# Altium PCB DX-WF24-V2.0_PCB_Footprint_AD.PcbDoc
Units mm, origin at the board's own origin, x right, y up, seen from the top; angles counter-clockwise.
Board outline 152.4 x 101.6 mm, 2 copper layers (Top, Bottom), stack 0.323 mm thick; 1 components, 0 nets, 29 pads, 0 vias.
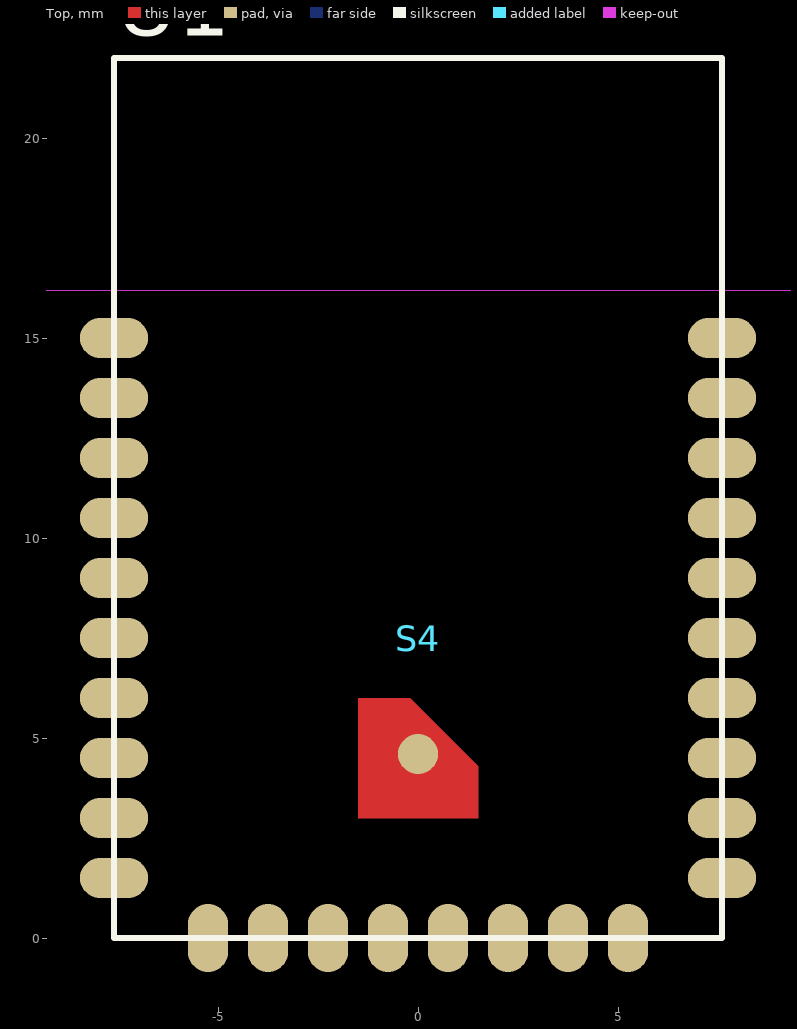
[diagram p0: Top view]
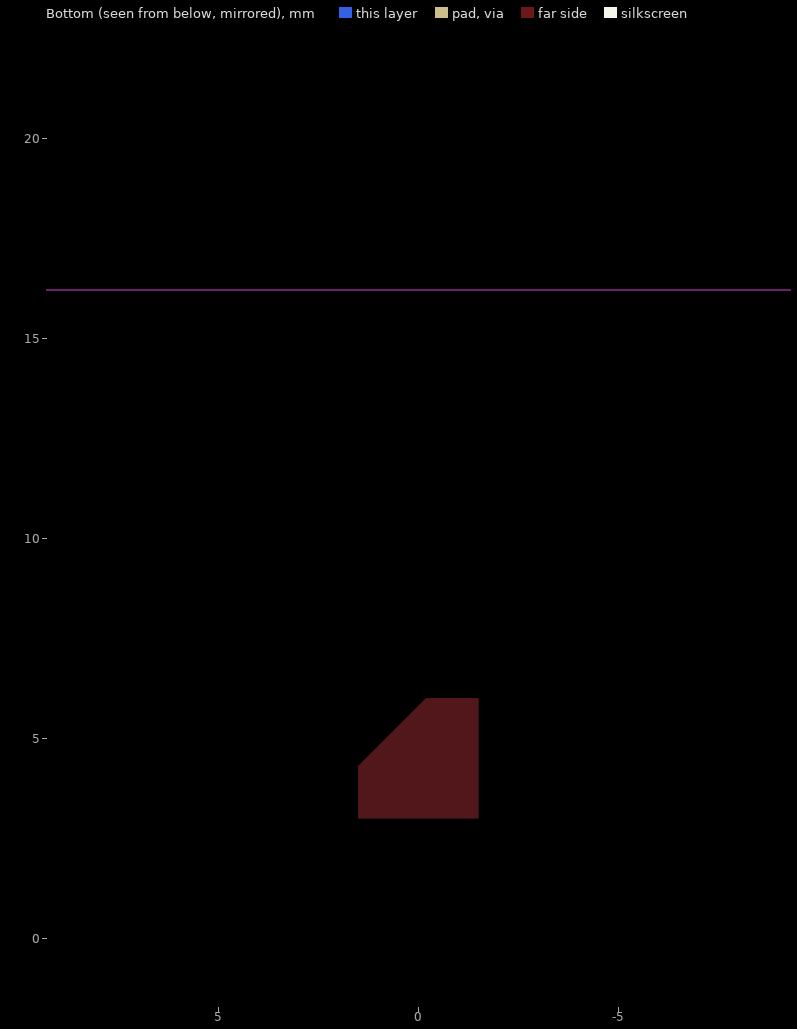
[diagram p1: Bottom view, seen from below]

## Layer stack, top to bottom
Solder Mask Top: solder mask 0.0102, Solder Resist, Dk 3.5
Top: signal copper 0.0343
Dielectric 1: dielectric 0.254, FR-4, Dk 4.3
Bottom: signal copper 0.0343
Solder Mask Bottom: solder mask 0.0102, Solder Resist, Dk 3.5

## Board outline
-694.363,-676.631 -541.963,-676.631 -541.963,-575.031 -694.363,-575.031

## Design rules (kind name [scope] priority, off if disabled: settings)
Clearance "'Default' PADS rule_17" [All] p1: gap=0.152 ignorepadtopadclearanceinfootprint=FALSE except(0: Arc-Hole Track-Hole SMDPad-Hole THPad-Hole Via-Hole Fill-Hole Poly-Hole Region-Hole Text-Hole)
Clearance "'Default' PADS rule_16" [InPolygon vs InPolygon] p2: gap=0.2 ignorepadtopadclearanceinfootprint=FALSE except(0: Arc-Hole Track-Hole SMDPad-Hole THPad-Hole Via-Hole Fill-Hole Poly-Hole Region-Hole Text-Hole)
Clearance "'Default' PADS rule_15" [All] p3: gap=0.152 ignorepadtopadclearanceinfootprint=FALSE except(0: Arc-Hole Track-Hole SMDPad-Hole THPad-Hole Via-Hole Fill-Hole Poly-Hole Region-Hole Text-Hole)
ComponentClearance "'Default' PADS rule_12" [All] p1: gap=0 collisioncheckmode=3 verticalgap=0.254 showdistances=FALSE
FlightTimeFalling "'Default' PADS rule_10" [All] p1: maximum=10.00
FlightTimeRising "'Default' PADS rule_9" [All] p1: maximum=10.00
Length "'Default' PADS rule_5" [All] p1: maxlimit=1270 minlimit=0
MatchedLengths "'Default' PADS rule_11" [InNetClass('All Nets')] p1: tolerance=5.08 checknetsindiffpair=TRUE checkdiffpairvsdiffpair=FALSE checkxsignals=FALSE checkothers=FALSE
MaxMinImpedance "'Default' PADS rule_8" [All] p1: minimum=50.00 maximum=150.0
ParallelSegment "'Default' PADS rule_7" [All] p1: limit=25.4 gap=5.08
ParallelSegment "'Default' PADS rule_6" [All] p2: limit=25.4 gap=5.08
PlaneClearance "'Default' PADS rule_14" [All] p1: clearance=0.2
PlaneConnect "Power Plane Connect Style - Via from round thru-hole global defaults" [IsVia] p1: planeconnectstyle=Direct reliefexpansion=0.508 reliefentries=4 reliefconductorwidth=0.381 reliefairgap=0.254
PlaneConnect "Power Plane Connect Style - Round thru-hole pad from global defaults" [IsPad And OnMultiLayer And (PadShape_MidLayer1 = 'Round') And (PadXSize_MidLayer1 = PadYSize_MidLayer1)] p2: planeconnectstyle=Direct reliefexpansion=0.508 reliefentries=4 reliefconductorwidth=0.381 reliefairgap=0.254
PlaneConnect "Power Plane Connect Style - Square thru-hole pad from global defaults" [IsPad And OnMultiLayer And ((PadShape_MidLayer1 = 'Rectangular') Or (PadShape_MidLayer1 = 'Octagonal') Or (PadShape_MidLayer1 = 'Rounded Rectangle')) And (PadXSize_MidLayer1 = PadYSize_MidLayer1)] p3: planeconnectstyle=Direct reliefexpansion=0.508 reliefentries=4 reliefconductorwidth=0.381 reliefairgap=0.254
PlaneConnect "Power Plane Connect Style - Rect thru-hole pad from global defaults" [IsPad And OnMultiLayer And ((PadShape_MidLayer1 = 'Rectangular') Or (PadShape_MidLayer1 = 'Octagonal') Or (PadShape_MidLayer1 = 'Rounded Rectangle')) And (PadXSize_MidLayer1 <> PadYSize_MidLayer1)] p4: planeconnectstyle=Direct reliefexpansion=0.508 reliefentries=4 reliefconductorwidth=0.381 reliefairgap=0.254
PlaneConnect "Power Plane Connect Style - Square-rect thru-hole pad from global defaults" [IsPad And OnMultiLayer And (PadShape_MidLayer1 = 'Rounded Rectangle') And (PadXSize_MidLayer1 = PadYSize_MidLayer1) And (Pad_CornerRadius_MidLayer1 = '0%')] p5: planeconnectstyle=Direct reliefexpansion=0.508 reliefentries=4 reliefconductorwidth=0.381 reliefairgap=0.254
PlaneConnect "Power Plane Connect Style - Oval thru-hole pad from global defaults" [IsPad And OnMultiLayer And (PadShape_MidLayer1 = 'Round') And (PadXSize_MidLayer1 <> PadYSize_MidLayer1)] p6: planeconnectstyle=Direct reliefexpansion=0.508 reliefentries=4 reliefconductorwidth=0.381 reliefairgap=0.254
PlaneConnect "Power Plane Connect Style - Round-oval thru-hole pad from global defaults" [IsPad And OnMultiLayer And (PadShape_MidLayer1 = 'Rounded Rectangle') And (PadXSize_MidLayer1 = PadYSize_MidLayer1) And (Pad_CornerRadius_MidLayer1 = '100%')] p7: planeconnectstyle=Direct reliefexpansion=0.508 reliefentries=4 reliefconductorwidth=0.381 reliefairgap=0.254
PolygonConnect "Polygon Connect Style - Bottom Round SMD from global defaults" [IsSMTPin And (PadShape_BottomLayer = 'Round') And (PadXSize_BottomLayer = PADYSize_BottomLayer) vs Layer = 'Bottom'] p1: connectstyle=Direct reliefconductorwidth=0.254 reliefentries=4 polygonreliefangle="45 Angle" airgapwidth=0.254
PolygonConnect "Polygon Connect Style - Top Round SMD from global defaults" [IsSMTPin And (PadShape_TopLayer = 'Round') And (PadXSize_TopLayer = PADYSize_TopLayer) vs Layer = 'Top'] p2: connectstyle=Direct reliefconductorwidth=0.254 reliefentries=4 polygonreliefangle="45 Angle" airgapwidth=0.254
PolygonConnect "Polygon Connect Style - Bottom Square SMD from global defaults 1" [IsSMTPin And (PadShape_BottomLayer = 'Rectangular') And (PadXSize_BottomLayer = PADYSize_BottomLayer) vs Layer = 'Bottom'] p3: connectstyle=Direct reliefconductorwidth=0.254 reliefentries=4 polygonreliefangle="45 Angle" airgapwidth=0.254
PolygonConnect "Polygon Connect Style - Bottom Square SMD from global defaults 2" [IsSMTPin And (PadShape_BottomLayer = 'Octagonal') And (PadXSize_BottomLayer = PADYSize_BottomLayer) vs Layer = 'Bottom'] p4: connectstyle=Direct reliefconductorwidth=0.254 reliefentries=4 polygonreliefangle="45 Angle" airgapwidth=0.254
PolygonConnect "Polygon Connect Style - Bottom Square SMD from global defaults 3" [IsSMTPin And (PadShape_BottomLayer = 'Rounded Rectangle') And (PadXSize_BottomLayer = PADYSize_BottomLayer) vs Layer = 'Bottom'] p5: connectstyle=Direct reliefconductorwidth=0.254 reliefentries=4 polygonreliefangle="45 Angle" airgapwidth=0.254
PolygonConnect "Polygon Connect Style - Top Square SMD from global defaults 1" [IsSMTPin And (PadShape_TopLayer = 'Rectangular') And (PadXSize_TopLayer = PADYSize_TopLayer) vs Layer = 'Top'] p6: connectstyle=Direct reliefconductorwidth=0.254 reliefentries=4 polygonreliefangle="45 Angle" airgapwidth=0.254
PolygonConnect "Polygon Connect Style - Top Square SMD from global defaults 2" [IsSMTPin And (PadShape_TopLayer = 'Octagonal') And (PadXSize_TopLayer = PADYSize_TopLayer) vs Layer = 'Top'] p7: connectstyle=Direct reliefconductorwidth=0.254 reliefentries=4 polygonreliefangle="45 Angle" airgapwidth=0.254
PolygonConnect "Polygon Connect Style - Top Square SMD from global defaults 3" [IsSMTPin And (PadShape_TopLayer = 'Rounded Rectangle') And (PadXSize_TopLayer = PADYSize_TopLayer) vs Layer = 'Top'] p8: connectstyle=Direct reliefconductorwidth=0.254 reliefentries=4 polygonreliefangle="45 Angle" airgapwidth=0.254
PolygonConnect "Polygon Connect Style - Bottom Rect SMD from global defaults 1" [IsSMTPin And (PadShape_BottomLayer = 'Rectangular') And (PadXSize_BottomLayer <> PADYSize_BottomLayer) vs Layer = 'Bottom'] p9: connectstyle=Direct reliefconductorwidth=0.254 reliefentries=4 polygonreliefangle="45 Angle" airgapwidth=0.254
PolygonConnect "Polygon Connect Style - Bottom Rect SMD from global defaults 2" [IsSMTPin And (PadShape_BottomLayer = 'Octagonal') And (PadXSize_BottomLayer <> PADYSize_BottomLayer) vs Layer = 'Bottom'] p10: connectstyle=Direct reliefconductorwidth=0.254 reliefentries=4 polygonreliefangle="45 Angle" airgapwidth=0.254
PolygonConnect "Polygon Connect Style - Bottom Rect SMD from global defaults 3" [IsSMTPin And (PadShape_BottomLayer = 'Rounded Rectangle') And (PadXSize_BottomLayer <> PADYSize_BottomLayer) vs Layer = 'Bottom'] p11: connectstyle=Direct reliefconductorwidth=0.254 reliefentries=4 polygonreliefangle="45 Angle" airgapwidth=0.254
PolygonConnect "Polygon Connect Style - Bottom Square-rect SMD pad from global defaults" [IsSMTPin And (PadShape_BottomLayer = 'Rounded Rectangle') And (PadXSize_BottomLayer = PADYSize_BottomLayer) And (Pad_CornerRadius_BottomLayer = '0%') vs Layer = 'Bottom'] p12: connectstyle=Direct reliefconductorwidth=0.254 reliefentries=4 polygonreliefangle="45 Angle" airgapwidth=0.254
PolygonConnect "Polygon Connect Style - Top Rect SMD from global defaults 1" [IsSMTPin And (PadShape_TopLayer = 'Rectangular') And (PadXSize_TopLayer <> PADYSize_TopLayer) vs Layer = 'Top'] p13: connectstyle=Direct reliefconductorwidth=0.254 reliefentries=4 polygonreliefangle="45 Angle" airgapwidth=0.254
PolygonConnect "Polygon Connect Style - Top Rect SMD from global defaults 2" [IsSMTPin And (PadShape_TopLayer = 'Octagonal') And (PadXSize_TopLayer <> PADYSize_TopLayer) vs Layer = 'Top'] p14: connectstyle=Direct reliefconductorwidth=0.254 reliefentries=4 polygonreliefangle="45 Angle" airgapwidth=0.254
PolygonConnect "Polygon Connect Style - Top Rect SMD from global defaults 3" [IsSMTPin And (PadShape_TopLayer = 'Rounded Rectangle') And (PadXSize_TopLayer <> PADYSize_TopLayer) vs Layer = 'Top'] p15: connectstyle=Direct reliefconductorwidth=0.254 reliefentries=4 polygonreliefangle="45 Angle" airgapwidth=0.254
PolygonConnect "Polygon Connect Style - Top Square-rect SMD pad from global defaults" [IsSMTPin And (PadShape_TopLayer = 'Rounded Rectangle') And (PadXSize_TopLayer = PADYSize_TopLayer) And (Pad_CornerRadius_TopLayer = '0%') vs Layer = 'Top'] p16: connectstyle=Direct reliefconductorwidth=0.254 reliefentries=4 polygonreliefangle="45 Angle" airgapwidth=0.254
PolygonConnect "Polygon Connect Style - Bottom Oval SMD from global defaults" [IsSMTPin And (PadShape_BottomLayer = 'Round') And (PadXSize_BottomLayer <> PADYSize_BottomLayer) vs Layer = 'Bottom'] p17: connectstyle=Direct reliefconductorwidth=0.254 reliefentries=4 polygonreliefangle="45 Angle" airgapwidth=0.254
PolygonConnect "Polygon Connect Style - Bottom Round-oval SMD pad from global defaults" [IsSMTPin And (PadShape_BottomLayer = 'Rounded Rectangle') And (PadXSize_BottomLayer = PADYSize_BottomLayer) And (Pad_CornerRadius_BottomLayer = '100%') vs Layer = 'Bottom'] p18: connectstyle=Direct reliefconductorwidth=0.254 reliefentries=4 polygonreliefangle="45 Angle" airgapwidth=0.254
PolygonConnect "Polygon Connect Style - Top Oval SMD from global defaults" [IsSMTPin And (PadShape_TopLayer = 'Round') And (PadXSize_TopLayer <> PADYSize_TopLayer) vs Layer = 'Top'] p19: connectstyle=Direct reliefconductorwidth=0.254 reliefentries=4 polygonreliefangle="45 Angle" airgapwidth=0.254
PolygonConnect "Polygon Connect Style - Top Round-oval SMD pad from global defaults" [IsSMTPin And (PadShape_TopLayer = 'Rounded Rectangle') And (PadXSize_TopLayer = PADYSize_TopLayer) And (Pad_CornerRadius_TopLayer = '100%') vs Layer = 'Top'] p20: connectstyle=Direct reliefconductorwidth=0.254 reliefentries=4 polygonreliefangle="45 Angle" airgapwidth=0.254
PolygonConnect "Polygon Connect Style - Via from round thru-hole global defaults_18" [IsVia] p21: connectstyle=Direct reliefconductorwidth=0.381 reliefentries=4 polygonreliefangle="45 Angle" airgapwidth=0.254
PolygonConnect "Polygon Connect Style - Bottom Round thru-hole pad from global defaults" [IsPad And OnMultiLayer And (PadShape_BottomLayer = 'Round') And (PadXSize_BottomLayer = PADYSize_BottomLayer) vs Layer = 'Bottom'] p22: connectstyle=Direct reliefconductorwidth=0.381 reliefentries=4 polygonreliefangle="45 Angle" airgapwidth=0.254
PolygonConnect "Polygon Connect Style - Via from round thru-hole global defaults" [IsVia] p23: connectstyle=Direct reliefconductorwidth=0.381 reliefentries=4 polygonreliefangle="45 Angle" airgapwidth=0.254
PolygonConnect "Polygon Connect Style - Top Round thru-hole pad from global defaults" [IsPad And OnMultiLayer And (PadShape_TopLayer = 'Round') And (PadXSize_TopLayer = PADYSize_TopLayer) vs Layer = 'Top'] p24: connectstyle=Direct reliefconductorwidth=0.381 reliefentries=4 polygonreliefangle="45 Angle" airgapwidth=0.254
PolygonConnect "Polygon Connect Style - Bottom Square thru-hole pad from global defaults" [IsPad And OnMultiLayer And ((PadShape_BottomLayer = 'Rectangular') Or (PadShape_BottomLayer = 'Octagonal') Or (PadShape_BottomLayer = 'Rounded Rectangle')) And (PadXSize_BottomLayer = PADYSize_BottomLayer) vs Layer = 'Bottom'] p25: connectstyle=Direct reliefconductorwidth=0.381 reliefentries=4 polygonreliefangle="45 Angle" airgapwidth=0.254
PolygonConnect "Polygon Connect Style - Top Square thru-hole pad from global defaults" [IsPad And OnMultiLayer And ((PadShape_TopLayer = 'Rectangular') Or (PadShape_TopLayer = 'Octagonal') Or (PadShape_TopLayer = 'Rounded Rectangle')) And (PadXSize_TopLayer = PADYSize_TopLayer) vs Layer = 'Top'] p26: connectstyle=Direct reliefconductorwidth=0.381 reliefentries=4 polygonreliefangle="45 Angle" airgapwidth=0.254
PolygonConnect "Polygon Connect Style - Bottom Rect thru-hole pad from global defaults" [IsPad And OnMultiLayer And ((PadShape_BottomLayer = 'Rectangular') Or (PadShape_BottomLayer = 'Octagonal') Or (PadShape_BottomLayer = 'Rounded Rectangle')) And (PadXSize_BottomLayer <> PADYSize_BottomLayer) vs Layer = 'Bottom'] p27: connectstyle=Direct reliefconductorwidth=0.381 reliefentries=4 polygonreliefangle="45 Angle" airgapwidth=0.254
PolygonConnect "Polygon Connect Style - Bottom Square-rect thru-hole pad from global defaults" [IsPad And OnMultiLayer And (PadShape_BottomLayer = 'Rounded Rectangle') And (PadXSize_BottomLayer = PADYSize_BottomLayer) And (Pad_CornerRadius_BottomLayer = '0%') vs Layer = 'Bottom'] p28: connectstyle=Direct reliefconductorwidth=0.381 reliefentries=4 polygonreliefangle="45 Angle" airgapwidth=0.254
PolygonConnect "Polygon Connect Style - Top Rect thru-hole pad from global defaults" [IsPad And OnMultiLayer And ((PadShape_TopLayer = 'Rectangular') Or (PadShape_TopLayer = 'Octagonal') Or (PadShape_TopLayer = 'Rounded Rectangle')) And (PadXSize_TopLayer <> PADYSize_TopLayer) vs Layer = 'Top'] p29: connectstyle=Direct reliefconductorwidth=0.381 reliefentries=4 polygonreliefangle="45 Angle" airgapwidth=0.254
PolygonConnect "Polygon Connect Style - Top Square-rect thru-hole pad from global defaults" [IsPad And OnMultiLayer And (PadShape_TopLayer = 'Rounded Rectangle') And (PadXSize_TopLayer = PADYSize_TopLayer) And (Pad_CornerRadius_TopLayer = '0%') vs Layer = 'Top'] p30: connectstyle=Direct reliefconductorwidth=0.381 reliefentries=4 polygonreliefangle="45 Angle" airgapwidth=0.254
PolygonConnect "Polygon Connect Style - Bottom Oval thru-hole pad from global defaults" [IsPad And OnMultiLayer And (PadShape_BottomLayer = 'Round') And (PadXSize_BottomLayer <> PADYSize_BottomLayer) vs Layer = 'Bottom'] p31: connectstyle=Direct reliefconductorwidth=0.381 reliefentries=4 polygonreliefangle="45 Angle" airgapwidth=0.254
PolygonConnect "Polygon Connect Style - Bottom Round-oval thru-hole pad from global defaults" [IsPad And OnMultiLayer And (PadShape_BottomLayer = 'Rounded Rectangle') And (PadXSize_BottomLayer = PADYSize_BottomLayer) And (Pad_CornerRadius_BottomLayer = '100%') vs Layer = 'Bottom'] p32: connectstyle=Direct reliefconductorwidth=0.381 reliefentries=4 polygonreliefangle="45 Angle" airgapwidth=0.254
PolygonConnect "Polygon Connect Style - Top Oval thru-hole pad from global defaults" [IsPad And OnMultiLayer And (PadShape_TopLayer = 'Round') And (PadXSize_TopLayer <> PADYSize_TopLayer) vs Layer = 'Top'] p33: connectstyle=Direct reliefconductorwidth=0.381 reliefentries=4 polygonreliefangle="45 Angle" airgapwidth=0.254
PolygonConnect "Polygon Connect Style - Top Round-oval thru-hole pad from global defaults" [IsPad And OnMultiLayer And (PadShape_TopLayer = 'Rounded Rectangle') And (PadXSize_TopLayer = PADYSize_TopLayer) And (Pad_CornerRadius_TopLayer = '100%') vs Layer = 'Top'] p34: connectstyle=Direct reliefconductorwidth=0.381 reliefentries=4 polygonreliefangle="45 Angle" airgapwidth=0.254
PolygonConnect [All] p35: connectstyle=Relief reliefconductorwidth=0.254 reliefentries=4 polygonreliefangle="90 Angle" airgapwidth=0.254
RoutingLayers "'Default' PADS rule_3" [All] p1: top layer_v5=TRUE bottom layer_v5=TRUE
RoutingPriority "'Default' PADS rule_2" [All] p1: routingpriority=3
RoutingTopology "'Default' PADS rule" [All] p1: topology=Shortest
RoutingVias "'Default' PADS rule_4" [All] p1: holewidth=0.23 width=0.5 viastyle="Through Hole" minholewidth=0.23 minwidth=0.5 maxholewidth=0.23 maxwidth=0.5
SolderMaskExpansion [All] p1: expansion=0.102 istentingtop=FALSE
Width "'Default' PADS rule_13" [All] p1: maxlimit=0.152 minlimit=0.152 preferedwidth=0.152
24 further rules are at their usual default settings.

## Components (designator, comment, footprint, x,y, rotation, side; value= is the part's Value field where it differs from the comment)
S4 "DX-WF24-SMT" DX-WF24-SMT 0,0 r0 top

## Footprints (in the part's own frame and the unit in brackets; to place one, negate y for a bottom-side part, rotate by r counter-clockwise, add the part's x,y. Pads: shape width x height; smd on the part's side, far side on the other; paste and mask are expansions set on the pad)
DX-WF24-SMT [mm]
  oval 1.7x1 smd: 1(-7.6,15) 2(-7.6,13.5) 3(-7.6,12) 4(-7.6,10.5) 5(-7.6,9) 6(-7.6,7.5) 7(-7.6,6) 8(-7.6,4.5) 9(-7.6,3) 10(-7.6,1.5) 19(7.6,1.5) 20(7.6,3) 21(7.6,4.5) 22(7.6,6) 23(7.6,7.5) 24(7.6,9) 25(7.6,10.5) 26(7.6,12) 27(7.6,13.5) 28(7.6,15)
  oval 1x1.7 smd: 11(-5.25,0) 12(-3.75,0) 13(-2.25,0) 14(-0.75,0) 15(0.75,0) 16(2.25,0) 17(3.75,0) 18(5.25,0)
  round 1 smd: 29(0,4.6)
  Top region: -1.5,6 -0.2,6 1.5,4.3 1.5,3 -1.5,3 -1.5,6
  silkscreen extent -7.6,0 7.6,22

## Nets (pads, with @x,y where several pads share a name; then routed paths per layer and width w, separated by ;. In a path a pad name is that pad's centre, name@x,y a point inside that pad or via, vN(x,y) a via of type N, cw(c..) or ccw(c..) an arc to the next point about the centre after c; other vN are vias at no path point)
pads on no net: S4.1 S4.2 S4.3 S4.4 S4.5 S4.6 S4.7 S4.8 S4.9 S4.10 S4.11 S4.12 S4.13 S4.14 S4.15 S4.16 S4.17 S4.18 S4.19 S4.20 S4.21 S4.22 S4.23 S4.24 S4.25 S4.26 S4.27 S4.28 S4.29

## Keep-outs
Keep-Out Layer:
  region: -12.7,27.1 -12.7,16.2 12.7,16.2 12.7,27.1

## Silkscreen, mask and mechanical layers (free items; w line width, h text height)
Silkscreen Top:
  text "U1" at -7.546,22.554 h1.52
